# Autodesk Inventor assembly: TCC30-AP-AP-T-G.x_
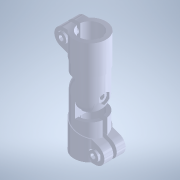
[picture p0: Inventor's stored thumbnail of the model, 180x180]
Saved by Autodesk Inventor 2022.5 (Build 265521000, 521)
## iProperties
Created: 2023-09
Part Number: TCC30-AP-AP-T-G.x_
Document SubType Name: Assembly
Designer: ImaoCorp
Sending System: SOLIDWORKS 2021-2021301
MC: AMD64
MC_MODEL: Intel64 Family 6 Model 60 Stepping 3, GenuineIntel
OS: Windows_NT
FRU: Parasolid Version 32.1, build 255,  1- 1-2021
FORMAT: text
GUISE: transmit
KEY: TCC30-AP-AP-T-G
FILE: TCC30-AP-AP-T-G.x_t
DATE: Fri Sep 15 15:35:31 2023
Author: ImaoCorp
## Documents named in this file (9)
- X:\14_SW2022-Inv2022\00_全2023-1023新製品(TCC)まで\t\tcc30-ap-ap-t-g\TCC30-AP-AP-T-G.iam
- X:\14_SW2022-Inv2022\00_全2023-1023新製品(TCC)まで\t\tcc30-ap-ap-t-g\TCC30-AP-AP-T-G_01.ipt
- X:\14_SW2022-Inv2022\00_全2023-1023新製品(TCC)まで\t\tcc30-ap-ap-t-g\TCC30-AP-AP-T-G_05.ipt
- X:\14_SW2022-Inv2022\00_全2023-1023新製品(TCC)まで\t\tcc30-ap-ap-t-g\TCC30-AP-AP-T-G_06.ipt
- X:\14_SW2022-Inv2022\00_全2023-1023新製品(TCC)まで\t\tcc30-ap-ap-t-g\TCC30-AP-AP-T-G_07.ipt
- X:\14_SW2022-Inv2022\00_全2023-1023新製品(TCC)まで\t\tcc30-ap-ap-t-g\TCC30-AP-AP-T-G_08.ipt
- X:\14_SW2022-Inv2022\00_全2023-1023新製品(TCC)まで\t\tcc30-ap-ap-t-g\TCC30-AP-AP-T-G_03.ipt
- X:\14_SW2022-Inv2022\00_全2023-1023新製品(TCC)まで\t\tcc30-ap-ap-t-g\TCC30-AP-AP-T-G_02.ipt
- X:\14_SW2022-Inv2022\00_全2023-1023新製品(TCC)まで\t\tcc30-ap-ap-t-g\TCC30-AP-AP-T-G_04.ipt
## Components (8 placed, 8 different names)
1. TCC30-AP-AP-T-G_01
2. TCC30-AP-AP-T-G_05
3. TCC30-AP-AP-T-G_06
4. TCC30-AP-AP-T-G_07
5. TCC30-AP-AP-T-G_08
6. TCC30-AP-AP-T-G_03
7. TCC30-AP-AP-T-G_02
8. TCC30-AP-AP-T-G_04
